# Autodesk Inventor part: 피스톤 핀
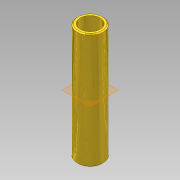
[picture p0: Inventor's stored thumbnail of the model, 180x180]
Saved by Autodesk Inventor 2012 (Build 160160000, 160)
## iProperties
Manager: KYOUNG IL JANG
Company: 한국ATC센터
Created: 2012-10
Part Number: 피스톤 핀
Document SubType Name: Modeling
Density: 1 g/cm^3
Checked By: KYOUNG IL JANG
Vendor: CBT Solutions
Designer: KYOUNG IL JANG
Material: 기본값
Author: KYOUNG IL JANG
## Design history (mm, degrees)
sketch "스케치1"
  geometry: C1 r 6.5 at (0, 0); C2 r 5 at (0, 0); 1 further point
  constraints: 2 centre point, 2 coincident
  dimensions: "d0" = 13 diameter of C1; "d1" = 1.5 radial gap between concentric circles of C1 C2
extrude "돌출1" new body sketch "스케치1" stored distance "d2" = 58; taper "d3" = 0 deg
chamfer "모따기1" distance "d4" = 0.5; stored, may be unused: second distance "d5" = 2, angle "d6" = 45 deg
node "솔리드1"
